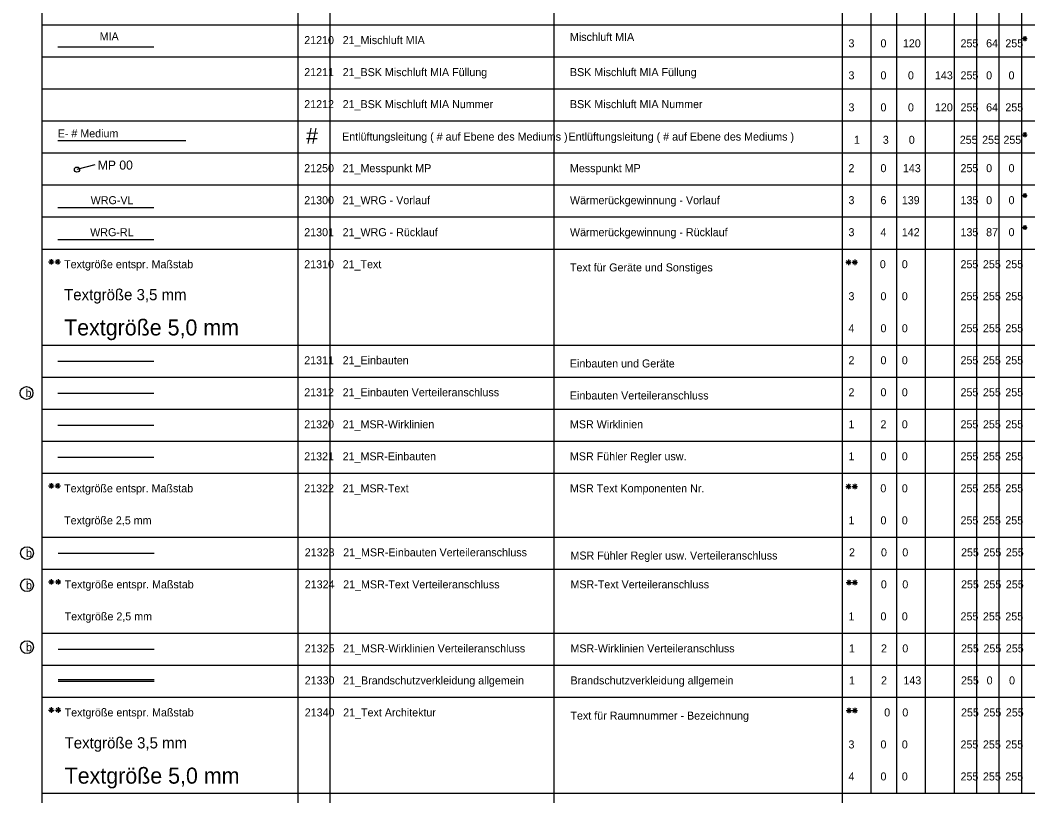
# Model space of a CAD drawing. Extents: x -12.9 to 27.6, y -77.8 to 7.2.
# Drawn here: x -0.34 to 15.4, y -59.54 to -47.43 of the extents above; entities that cross this region are included whole.
import ezdxf

# ---------------------------------------------------------------- set-up
doc = ezdxf.new("R2010")
doc.units = 0
for name, color, linetype in [('21_Brandschutzverkleidung allgemein', 7, 'Continuous'), ('21_Einbauten', 7, 'Continuous'), ('21_Einbauten Verteileranschluss', 7, 'Continuous'), ('21_Messpunkt MP', 7, 'Continuous'), ('21_Mischluft MIA', 7, 'Continuous'), ('21_MSR-Einbauten', 7, 'Continuous'), ('21_MSR-Einbauten Verteileranschluss', 7, 'Continuous'), ('21_MSR-Text', 7, 'Continuous'), ('21_MSR-Text Verteileranschluss', 7, 'Continuous'), ('21_MSR-Wirklinien', 7, 'Continuous'), ('21_MSR-Wirklinien Verteileranschluss', 7, 'Continuous'), ('21_Text', 7, 'Continuous'), ('21_Text Architektur', 7, 'Continuous'), ('21_WRG - Rücklauf', 7, 'Continuous'), ('21_WRG - Vorlauf', 7, 'Continuous'), ('21_z_freie_Ebene_01', 7, 'Continuous'), ('90_Alter Index', 7, 'Continuous'), ('Default', 7, 'Continuous')]:
    doc.layers.add(name, color=color, linetype=linetype)

msp = doc.modelspace()

# ---------------------------------------------------------------- linework, layer by layer
at = {"layer": '21_Brandschutzverkleidung allgemein'}
for p, q in [((0.258, -57.725), (1.758, -57.725)), ((0.258, -57.75), (1.758, -57.75))]:
    msp.add_line(p, q, dxfattribs=at)
at = {"layer": '21_Einbauten'}
msp.add_line((0.25, -52.75), (1.75, -52.75), dxfattribs=at)
at = {"layer": '21_Einbauten Verteileranschluss'}
msp.add_line((0.25, -53.25), (1.75, -53.25), dxfattribs=at)
at = {"layer": '21_Messpunkt MP'}
msp.add_line((0.828, -49.685), (0.551, -49.76), dxfattribs=at)
msp.add_circle((0.551, -49.76), 0.0405, dxfattribs=at)
at = {"layer": '21_Mischluft MIA'}
msp.add_line((0.25, -47.841), (1.75, -47.841), dxfattribs=at)
at = {"layer": '21_MSR-Einbauten'}
msp.add_line((0.25, -54.25), (1.75, -54.25), dxfattribs=at)
at = {"layer": '21_MSR-Einbauten Verteileranschluss'}
msp.add_line((0.258, -55.75), (1.758, -55.75), dxfattribs=at)
at = {"layer": '21_MSR-Wirklinien'}
msp.add_line((0.25, -53.75), (1.75, -53.75), dxfattribs=at)
at = {"layer": '21_MSR-Wirklinien Verteileranschluss'}
msp.add_line((0.258, -57.25), (1.758, -57.25), dxfattribs=at)
at = {"layer": '21_WRG - Rücklauf'}
msp.add_line((0.25, -50.85), (1.75, -50.85), dxfattribs=at)
at = {"layer": '21_WRG - Vorlauf'}
msp.add_line((0.25, -50.35), (1.75, -50.35), dxfattribs=at)
at = {"layer": '21_z_freie_Ebene_01'}
msp.add_line((0.25, -49.307), (2.25, -49.307), dxfattribs=at)
at = {"layer": '90_Alter Index'}
for centre in [(-0.237, -53.249), (-0.229, -55.749), (-0.229, -56.25), (-0.229, -57.218)]:
    msp.add_circle(centre, 0.1, dxfattribs=at)
at = {"layer": 'Default'}
for p, q in [((0, 0), (0, -73.5)), ((4, 0), (4, -73.5)), ((4.5, 0), (4.5, -73.5)), ((8, 0), (8, -73.5)), ((12.5, 0), (12.5, -73.5)), ((12.95, -0.35), (12.95, -59.5)), ((13.35, -0.35), (13.35, -59.5)), ((13.8, -0.35), (13.8, -59.5)), ((14.25, -0.35), (14.25, -59.5)), ((15.3, -0.35), (15.3, -59.5)), ((14.6, -0.75), (14.6, -59.5)), ((14.95, -0.75), (14.95, -59.5)), ((0, -47.5), (16.8, -47.5)), ((15.355, -47.677), (15.355, -47.753)), ((15.317, -47.715), (15.393, -47.715)), ((15.328, -47.688), (15.382, -47.742)), ((15.382, -47.688), (15.328, -47.742)), ((0, -48), (16.8, -48)), ((0, -48.5), (16.8, -48.5)), ((0, -49), (16.8, -49)), ((15.317, -49.215), (15.393, -49.215)), ((15.328, -49.188), (15.382, -49.242)), ((15.382, -49.188), (15.328, -49.242)), ((15.355, -49.177), (15.355, -49.253)), ((0, -49.5), (16.8, -49.5)), ((0, -50), (16.8, -50)), ((15.317, -50.165), (15.393, -50.165)), ((15.328, -50.138), (15.382, -50.192)), ((15.382, -50.138), (15.328, -50.192)), ((15.355, -50.127), (15.355, -50.203)), ((0, -50.5), (16.8, -50.5)), ((15.317, -50.665), (15.393, -50.665)), ((15.328, -50.638), (15.382, -50.692)), ((15.382, -50.638), (15.328, -50.692)), ((15.355, -50.627), (15.355, -50.703)), ((0, -51), (16.8, -51)), ((0.108, -51.2), (0.192, -51.2)), ((0.12, -51.17), (0.18, -51.23)), ((0.18, -51.17), (0.12, -51.23)), ((0.15, -51.158), (0.15, -51.242)), ((0.208, -51.2), (0.292, -51.2)), ((0.22, -51.17), (0.28, -51.23)), ((0.28, -51.17), (0.22, -51.23)), ((0.25, -51.158), (0.25, -51.242)), ((12.558, -51.208), (12.642, -51.208)), ((12.57, -51.178), (12.63, -51.238)), ((12.63, -51.178), (12.57, -51.238)), ((12.6, -51.166), (12.6, -51.25)), ((12.658, -51.208), (12.742, -51.208)), ((12.67, -51.178), (12.73, -51.238)), ((12.73, -51.178), (12.67, -51.238)), ((12.7, -51.166), (12.7, -51.25)), ((0, -52.5), (16.8, -52.5)), ((0, -53), (16.8, -53)), ((0, -53.5), (16.8, -53.5)), ((0, -54), (16.8, -54)), ((0, -54.5), (16.8, -54.5)), ((0.108, -54.7), (0.192, -54.7)), ((0.12, -54.67), (0.18, -54.73)), ((0.18, -54.67), (0.12, -54.73)), ((0.15, -54.658), (0.15, -54.742)), ((0.208, -54.7), (0.292, -54.7)), ((0.22, -54.67), (0.28, -54.73)), ((0.28, -54.67), (0.22, -54.73)), ((0.25, -54.658), (0.25, -54.742)), ((12.558, -54.708), (12.642, -54.708)), ((12.57, -54.678), (12.63, -54.738)), ((12.63, -54.678), (12.57, -54.738)), ((12.6, -54.666), (12.6, -54.75)), ((12.658, -54.708), (12.742, -54.708)), ((12.67, -54.678), (12.73, -54.738)), ((12.73, -54.678), (12.67, -54.738)), ((12.7, -54.666), (12.7, -54.75)), ((0.008, -55.5), (16.808, -55.5)), ((0.015, -56), (16.808, -56)), ((0.12, -56.17), (0.18, -56.23)), ((0.18, -56.17), (0.12, -56.23)), ((0.15, -56.158), (0.15, -56.242)), ((0.228, -56.17), (0.287, -56.23)), ((0.287, -56.17), (0.228, -56.23)), ((0.258, -56.158), (0.258, -56.242)), ((12.578, -56.178), (12.637, -56.238)), ((12.637, -56.178), (12.578, -56.238)), ((12.608, -56.166), (12.608, -56.25)), ((12.67, -56.178), (12.73, -56.238)), ((12.73, -56.178), (12.67, -56.238)), ((12.7, -56.166), (12.7, -56.25)), ((0.108, -56.2), (0.192, -56.2)), ((0.216, -56.2), (0.3, -56.2)), ((12.566, -56.208), (12.65, -56.208)), ((12.658, -56.208), (12.742, -56.208)), ((0.008, -57), (16.808, -57)), ((0.008, -57.5), (16.808, -57.5)), ((0.008, -58), (16.808, -58)), ((0.108, -58.2), (0.192, -58.2)), ((0.12, -58.17), (0.18, -58.23)), ((0.18, -58.17), (0.12, -58.23)), ((0.15, -58.158), (0.15, -58.242)), ((0.216, -58.2), (0.3, -58.2)), ((0.228, -58.17), (0.287, -58.23)), ((0.287, -58.17), (0.228, -58.23)), ((0.258, -58.158), (0.258, -58.242)), ((12.566, -58.208), (12.65, -58.208)), ((12.578, -58.178), (12.637, -58.238)), ((12.637, -58.178), (12.578, -58.238)), ((12.608, -58.166), (12.608, -58.25)), ((12.658, -58.208), (12.742, -58.208)), ((12.67, -58.178), (12.73, -58.238)), ((12.73, -58.178), (12.67, -58.238)), ((12.7, -58.166), (12.7, -58.25)), ((0.008, -59.5), (16.808, -59.5))]:
    msp.add_line(p, q, dxfattribs=at)

# ---------------------------------------------------------------- texts
at = {"layer": '21_Messpunkt MP'}
msp.add_text('MP 00', height=0.1418, dxfattribs=at).set_placement((0.875, -49.76))
at = {"layer": '21_Mischluft MIA'}
msp.add_text('MIA', height=0.125, dxfattribs=at).set_placement((0.905, -47.741))
at = {"layer": '21_MSR-Text'}
msp.add_text('Textgröße 2,5 mm', height=0.125, dxfattribs=at).set_placement((0.35, -55.3))
at = {"layer": '21_MSR-Text Verteileranschluss'}
msp.add_text('Textgröße 2,5 mm', height=0.125, dxfattribs=at).set_placement((0.358, -56.8))
at = {"layer": '21_Text'}
for s, height, p in [('Textgröße 3,5 mm', 0.175, (0.35, -51.8)), ('Textgröße 5,0 mm', 0.25, (0.35, -52.35))]:
    msp.add_text(s, height=height, dxfattribs=at).set_placement(p)
at = {"layer": '21_Text Architektur'}
for s, height, p in [('Textgröße 3,5 mm', 0.175, (0.358, -58.8)), ('Textgröße 5,0 mm', 0.25, (0.358, -59.35))]:
    msp.add_text(s, height=height, dxfattribs=at).set_placement(p)
at = {"layer": '21_WRG - Rücklauf'}
msp.add_text('WRG-RL', height=0.125, dxfattribs=at).set_placement((0.757, -50.8))
at = {"layer": '21_WRG - Vorlauf'}
msp.add_text('WRG-VL', height=0.125, dxfattribs=at).set_placement((0.765, -50.3))
at = {"layer": '21_z_freie_Ebene_01'}
msp.add_text('E- # Medium', height=0.125, dxfattribs=at).set_placement((0.25, -49.257))
at = {"layer": '90_Alter Index'}
for p in [(-0.253, -53.311), (-0.245, -55.811), (-0.245, -56.313), (-0.245, -57.281)]:
    msp.add_text('b', height=0.125, dxfattribs=at).set_placement(p)
at = {"layer": 'Default'}
for s, height, p in [('21210', 0.125, (4.1, -47.8)), ('21_Mischluft MIA ', 0.125, (4.7, -47.8)), ('Mischluft MIA ', 0.125, (8.25, -47.75)), ('3', 0.125, (12.6, -47.85)), ('0', 0.125, (13.1, -47.85)), ('120', 0.125, (13.45, -47.85)), ('255', 0.125, (14.35, -47.85)), ('64', 0.125, (14.75, -47.85)), ('255', 0.125, (15.05, -47.85)), ('21211', 0.125, (4.1, -48.3)), ('21_BSK Mischluft MIA Füllung', 0.125, (4.7, -48.3)), ('BSK Mischluft MIA Füllung', 0.125, (8.25, -48.3)), ('3', 0.125, (12.6, -48.35)), ('0', 0.125, (13.1, -48.35)), ('0', 0.125, (13.529, -48.35)), ('143', 0.125, (13.95, -48.35)), ('255', 0.125, (14.35, -48.35)), ('0', 0.125, (14.75, -48.35)), ('0', 0.125, (15.1, -48.35)), ('21212', 0.125, (4.1, -48.8)), ('21_BSK Mischluft MIA Nummer', 0.125, (4.7, -48.8)), ('BSK Mischluft MIA Nummer', 0.125, (8.25, -48.8)), ('3', 0.125, (12.6, -48.85)), ('0', 0.125, (13.1, -48.85)), ('0', 0.125, (13.529, -48.85)), ('120', 0.125, (13.95, -48.85)), ('255', 0.125, (14.35, -48.85)), ('64', 0.125, (14.75, -48.85)), ('255', 0.125, (15.05, -48.85)), (' # ', 0.25, (4.036, -49.357)), (' Entlüftungsleitung ( # auf Ebene des Mediums )', 0.125, (4.645, -49.307)), (' Entlüftungsleitung ( # auf Ebene des Mediums )', 0.125, (8.182, -49.307)), ('1', 0.125, (12.686, -49.357)), ('3', 0.125, (13.136, -49.357)), ('0', 0.125, (13.542, -49.357)), ('255', 0.125, (14.338, -49.357)), ('255', 0.125, (14.687, -49.357)), ('255', 0.125, (15.02, -49.357)), ('21250', 0.125, (4.1, -49.8)), ('21_Messpunkt MP', 0.125, (4.7, -49.8)), ('Messpunkt MP', 0.125, (8.25, -49.8)), ('2', 0.125, (12.6, -49.8)), ('0 ', 0.125, (13.1, -49.8)), ('143', 0.125, (13.45, -49.8)), ('255', 0.125, (14.35, -49.8)), ('0', 0.125, (14.75, -49.8)), ('0', 0.125, (15.1, -49.8)), ('21300', 0.125, (4.1, -50.3)), ('21_WRG - Vorlauf', 0.125, (4.7, -50.3)), ('Wärmerückgewinnung - Vorlauf ', 0.125, (8.25, -50.3)), ('3', 0.125, (12.6, -50.3)), ('6', 0.125, (13.1, -50.3)), ('139', 0.125, (13.433, -50.3)), ('135', 0.125, (14.35, -50.3)), ('0', 0.125, (14.75, -50.3)), ('0', 0.125, (15.1, -50.3)), ('21301', 0.125, (4.1, -50.8)), ('21_WRG - Rücklauf', 0.125, (4.7, -50.8)), ('Wärmerückgewinnung - Rücklauf ', 0.125, (8.25, -50.8)), ('3', 0.125, (12.6, -50.8)), ('4', 0.125, (13.1, -50.8)), ('142', 0.125, (13.433, -50.8)), ('135', 0.125, (14.35, -50.8)), ('87', 0.125, (14.75, -50.8)), ('0', 0.125, (15.1, -50.8)), ('Textgröße entspr. Maßstab', 0.125, (0.35, -51.3)), ('21310', 0.125, (4.1, -51.3)), ('21_Text', 0.125, (4.7, -51.3)), ('Text für Geräte und Sonstiges', 0.125, (8.25, -51.35)), ('0', 0.125, (13.09, -51.3)), ('0', 0.125, (13.433, -51.3)), ('255', 0.125, (14.35, -51.3)), ('255', 0.125, (14.7, -51.3)), ('255', 0.125, (15.05, -51.3)), ('3', 0.125, (12.6, -51.8)), ('0', 0.125, (13.1, -51.8)), ('0', 0.125, (13.433, -51.8)), ('255', 0.125, (14.35, -51.8)), ('255', 0.125, (14.7, -51.8)), ('255', 0.125, (15.05, -51.8)), ('4', 0.125, (12.6, -52.3)), ('0', 0.125, (13.1, -52.3)), ('0', 0.125, (13.433, -52.3)), ('255', 0.125, (14.35, -52.3)), ('255', 0.125, (14.7, -52.3)), ('255', 0.125, (15.05, -52.3)), ('21311', 0.125, (4.1, -52.8)), ('21_Einbauten', 0.125, (4.7, -52.8)), ('Einbauten und Geräte', 0.125, (8.25, -52.85)), ('2', 0.125, (12.6, -52.8)), ('0', 0.125, (13.1, -52.8)), ('0', 0.125, (13.433, -52.8)), ('255', 0.125, (14.35, -52.8)), ('255', 0.125, (14.7, -52.8)), ('255', 0.125, (15.05, -52.8)), ('21312', 0.125, (4.1, -53.3)), ('21_Einbauten Verteileranschluss', 0.125, (4.7, -53.3)), ('2', 0.125, (12.6, -53.3)), ('0', 0.125, (13.1, -53.3)), ('0', 0.125, (13.433, -53.3)), ('255', 0.125, (14.35, -53.3)), ('255', 0.125, (14.7, -53.3)), ('255', 0.125, (15.05, -53.3)), ('Einbauten Verteileranschluss', 0.125, (8.25, -53.35)), ('21320', 0.125, (4.1, -53.8)), ('21_MSR-Wirklinien', 0.125, (4.7, -53.8)), ('MSR Wirklinien', 0.125, (8.25, -53.8)), ('1', 0.125, (12.6, -53.8)), ('2', 0.125, (13.1, -53.8)), ('0', 0.125, (13.433, -53.8)), ('255', 0.125, (14.35, -53.8)), ('255', 0.125, (14.7, -53.8)), ('255', 0.125, (15.05, -53.8)), ('21321', 0.125, (4.1, -54.3)), ('21_MSR-Einbauten', 0.125, (4.7, -54.3)), ('MSR Fühler Regler usw.', 0.125, (8.25, -54.3)), ('1', 0.125, (12.6, -54.3)), ('0', 0.125, (13.1, -54.3)), ('0', 0.125, (13.433, -54.3)), ('255', 0.125, (14.35, -54.3)), ('255', 0.125, (14.7, -54.3)), ('255', 0.125, (15.05, -54.3)), ('Textgröße entspr. Maßstab', 0.125, (0.35, -54.8)), ('21322', 0.125, (4.1, -54.8)), ('21_MSR-Text', 0.125, (4.7, -54.8)), ('MSR Text Komponenten Nr. ', 0.125, (8.25, -54.8)), ('0', 0.125, (13.098, -54.8)), ('0', 0.125, (13.433, -54.8)), ('255', 0.125, (14.35, -54.8)), ('255', 0.125, (14.7, -54.8)), ('255', 0.125, (15.05, -54.8)), ('1', 0.125, (12.6, -55.3)), ('0', 0.125, (13.1, -55.3)), ('0', 0.125, (13.433, -55.3)), ('255', 0.125, (14.35, -55.3)), ('255', 0.125, (14.7, -55.3)), ('255', 0.125, (15.05, -55.3)), ('21323', 0.125, (4.108, -55.8)), ('21_MSR-Einbauten Verteileranschluss', 0.125, (4.708, -55.8)), ('2', 0.125, (12.608, -55.8)), ('0', 0.125, (13.108, -55.8)), ('0', 0.125, (13.441, -55.8)), ('255', 0.125, (14.358, -55.8)), ('255', 0.125, (14.708, -55.8)), ('255', 0.125, (15.058, -55.8)), ('MSR Fühler Regler usw. Verteileranschluss', 0.125, (8.258, -55.85)), ('Textgröße entspr. Maßstab', 0.125, (0.358, -56.3)), ('21324', 0.125, (4.108, -56.3)), ('21_MSR-Text Verteileranschluss', 0.125, (4.708, -56.3)), ('MSR-Text Verteileranschluss', 0.125, (8.258, -56.3)), ('0', 0.125, (13.106, -56.3)), ('0', 0.125, (13.441, -56.3)), ('255', 0.125, (14.358, -56.3)), ('255', 0.125, (14.708, -56.3)), ('255', 0.125, (15.058, -56.3)), ('1', 0.125, (12.6, -56.8)), ('0', 0.125, (13.1, -56.8)), ('0', 0.125, (13.433, -56.8)), ('255', 0.125, (14.35, -56.8)), ('255', 0.125, (14.7, -56.8)), ('255', 0.125, (15.05, -56.8)), ('21325', 0.125, (4.108, -57.3)), ('21_MSR-Wirklinien Verteileranschluss', 0.125, (4.708, -57.3)), ('MSR-Wirklinien Verteileranschluss', 0.125, (8.258, -57.3)), ('1', 0.125, (12.608, -57.3)), ('2', 0.125, (13.108, -57.3)), ('0', 0.125, (13.441, -57.3)), ('255', 0.125, (14.358, -57.3)), ('255', 0.125, (14.708, -57.3)), ('255', 0.125, (15.058, -57.3)), ('21330', 0.125, (4.108, -57.8)), ('21_Brandschutzverkleidung allgemein', 0.125, (4.708, -57.8)), ('Brandschutzverkleidung allgemein', 0.125, (8.258, -57.8)), ('1', 0.125, (12.608, -57.8)), ('2', 0.125, (13.108, -57.8)), ('143', 0.125, (13.458, -57.8)), ('255', 0.125, (14.358, -57.8)), ('0', 0.125, (14.758, -57.8)), ('0', 0.125, (15.108, -57.8)), ('Textgröße entspr. Maßstab', 0.125, (0.358, -58.3)), ('21340', 0.125, (4.108, -58.3)), ('21_Text Architektur', 0.125, (4.708, -58.3)), ('Text für Raumnummer - Bezeichnung', 0.125, (8.258, -58.35)), ('0', 0.125, (13.158, -58.3)), ('0', 0.125, (13.441, -58.3)), ('255', 0.125, (14.358, -58.3)), ('255', 0.125, (14.708, -58.3)), ('255', 0.125, (15.058, -58.3)), ('3', 0.125, (12.6, -58.8)), ('0', 0.125, (13.1, -58.8)), ('0', 0.125, (13.433, -58.8)), ('255', 0.125, (14.35, -58.8)), ('255', 0.125, (14.7, -58.8)), ('255', 0.125, (15.05, -58.8)), ('4', 0.125, (12.6, -59.3)), ('0', 0.125, (13.1, -59.3)), ('0', 0.125, (13.433, -59.3)), ('255', 0.125, (14.35, -59.3)), ('255', 0.125, (14.7, -59.3)), ('255', 0.125, (15.05, -59.3))]:
    msp.add_text(s, height=height, dxfattribs=at).set_placement(p)

doc.saveas('drawing.dxf')
